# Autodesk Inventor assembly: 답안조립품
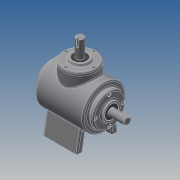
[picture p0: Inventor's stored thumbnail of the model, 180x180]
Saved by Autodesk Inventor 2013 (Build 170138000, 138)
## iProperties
Created: 2015-01
Part Number: 답안조립품
Document SubType Name: Assembly
Designer: kb543-154
Author: kb543-154
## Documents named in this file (15)
- C:\Users\kb543-154\Desktop\450105V1033\답안조립품.iam
- C:\Users\kb543-154\Desktop\450105V1033\메인 축.ipt
- 메인 축.ipt
- C:\Users\kb543-154\Desktop\450105V1033\키 5x5.ipt
- C:\Users\kb543-154\Desktop\450105V1033\메인 베벨기어.ipt
- C:\Users\kb543-154\Desktop\450105V1033\베어링 6203.ipt
- C:\Users\kb543-154\Desktop\450105V1033\1.본체.ipt
- C:\Users\kb543-154\Desktop\450105V1033\커버.ipt
- C:\Users\kb543-154\Desktop\450105V1033\오일실.ipt
- C:\Users\kb543-154\Desktop\450105V1033\서브 축.ipt
- 서브 축.ipt
- C:\Users\kb543-154\Desktop\450105V1033\키 4x4.ipt
- C:\Users\kb543-154\Desktop\450105V1033\서브 베벨기어.ipt
- C:\Users\kb543-154\Desktop\450105V1033\커버2.ipt
- C:\Users\kb543-154\Desktop\450105V1033\M4.ipt
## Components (13 placed, 2 different names)
1. 1.본체:1
2. M4:1
3. M4:2
4. M4:3
5. M4:4
6. M4:5
7. M4:6
8. M4:7
9. M4:8
10. M4:9
11. M4:10
12. M4:11
13. M4:12
